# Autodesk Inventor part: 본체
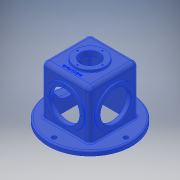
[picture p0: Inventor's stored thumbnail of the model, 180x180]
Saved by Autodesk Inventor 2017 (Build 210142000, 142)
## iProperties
Created: 2018-09
Part Number: 본체
Material: 알루미늄 6061
Document SubType Name: Modeling
Designer: mduedu
Density: 2.71 g/cm^3
Appearance: 기본값
Mass: 1123.29 g
Surface Area: 1247.23 cm^2
Volume: 414.5 cm^3
Author: mduedu
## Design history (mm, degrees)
sketch "스케치1"
  geometry: C1 r 90 at (0, 0); 1 further point
  constraints: 1 centre point, 1 coincident
  dimensions: "d85" = 180 diameter of C1
extrude "돌출1" new body sketch "스케치1" distance "d2" = 10; taper "d3" = 0 deg
sketch "스케치2"
  geometry: L1 (-52.5, -52.5)-(52.5, -52.5); L2 (52.5, -52.5)-(52.5, 52.5); L3 (52.5, 52.5)-(-52.5, 52.5); L4 (-52.5, 52.5)-(-52.5, -52.5); L5 (-52.5, -52.5)-(52.5, 52.5); L6 (52.5, -52.5)-(-52.5, 52.5); 1 further point
  constraints: 12 end point, 2 midpoint, 2 parallel, 1 horizontal, 1 perpendicular
  dimensions: "d4" = 105 distance of L3.end L2.end; "d5" = 105 distance of L2.end L1.end
extrude "돌출2" join sketch "스케치2" distance "d6" = 105; taper "d7" = 0 deg
node "작업 평면1"
sketch "스케치3"
  geometry: L1 (-52.5, 52.5)-(52.5, 52.5) reference; L2 (52.5, 52.5)-(52.5, -52.5) reference; L3 (52.5, -52.5)-(-52.5, -52.5) reference; L4 (-52.5, -52.5)-(-52.5, 52.5) reference; L5 (46.5, 46.5)-(-46.5, 46.5); L6 (-46.5, 46.5)-(-46.5, -46.5); L7 (-46.5, -46.5)-(46.5, -46.5); L8 (46.5, -46.5)-(46.5, 46.5); 1 further point
  constraints: 8 end point, 3 other
  dimensions: "d9" = 6 distance between parallel lines of L5 L1
extrude "돌출3" cut sketch "스케치3" stored distance "d10" = 105; taper "d11" = 0 deg
fillet "모깎기1" dims "d12" = 9
fillet "모깎기2" dims "d13" = 9
fillet "모깎기3" dims "d14" = 3
fillet "모깎기4" dims "d15" = 3
sketch "스케치4"
  geometry: C1 r 32 at (0, 0); 1 further point
  constraints: 1 centre point, 1 coincident
  dimensions: "d86" = 64 diameter of C1
extrude "돌출4" join sketch "스케치4" distance "d18" = 5; taper "d19" = 0 deg
fillet "모깎기6" dims "d21" = 1
sketch "스케치5"
  geometry: C1 r 20 at (0, 0); 1 further point
  constraints: 1 centre point, 1 coincident
  dimensions: "d22" = 40 diameter of C1
extrude "돌출5" cut sketch "스케치5" stored distance "d23" = 5; taper "d24" = 0 deg
sketch "스케치6"
  geometry: L1 (-46.5, -10)-(133.5, -10) reference; C1 r 42 at (43.5, 47.5); 1 further point
  constraints: 1 centre point, 1 vertical alignment
  dimensions: "d87" = 84 diameter of C1; "d88" = 57.5 distance from line of C1.centre L1
extrude "돌출6" join sketch "스케치6" distance "d28" = 3; taper "d29" = 0 deg
sketch "스케치7"
  geometry: C1 r 32.5 at (43.5, 47.5); 1 further point
  constraints: 1 centre point, 1 vertical alignment
  dimensions: "d32" = 65 diameter of C1; "d33" = 57.5 distance of C1.centre point (43.5, -10)
extrude "돌출7" cut sketch "스케치7" stored distance "d34" = 3; taper "d35" = 0 deg
fillet "모깎기9" dims "d36" = 1
sketch "스케치8"
  geometry: L1 (-46.5, -10)-(133.5, -10) reference; C1 r 32.5 at (43.5, 47.5); C2 r 42 at (43.5, 47.5); 4 further points
  constraints: 2 centre point, 2 coincident, 2 vertical alignment, 1 concentric, 1 midpoint
  dimensions: "d40" = 65 diameter of C1; "d90" = 84 diameter of C2; "d91" = 57.5 distance from line of point (43.5, 47.5) L1
extrude "돌출8" join sketch "스케치8" distance "d41" = 3; taper "d42" = 0 deg
extrude "돌출9" cut sketch "스케치8" stored distance "d44" = 3; taper "d45" = 0 deg
fillet "모깎기11" dims "d46" = 1
sketch "스케치14" dims "d93" = 74
  geometry: C1 r 42 at (0, 0) reference; 2 further points
  constraints: 2 vertical alignment, 1 coincident, 2 other
hole "구멍5" sketch "스케치14" at (0, 37) diameter "d95" = 3.242; stored, may be unused: countersink angle "d99" = 90 deg, drill point angle "d101" = 118 deg; dims "d96" = 6, "d97" = 4, "d98" = 2, "d100" = 8
sketch "스케치9" dims "d106" = 74
  geometry: C1 r 32.5 at (43.5, 47.5) reference; 2 further points
  constraints: 2 vertical alignment, 1 coincident, 2 other
hole "구멍1" sketch "스케치9" at (43.5, 84.5) diameter "d47" = 3.242; stored, may be unused: countersink angle "d51" = 90 deg, drill point angle "d53" = 118 deg; dims "d48" = 6, "d49" = 4, "d50" = 2, "d52" = 9
sketch "스케치11" dims "d110" = 54
  geometry: C1 r 20 at (0, 0) reference; 2 further points
  constraints: 2 horizontal alignment, 1 coincident, 2 other
hole "구멍3" sketch "스케치11" at (27, 0) diameter "d61" = 3.242; stored, may be unused: countersink angle "d65" = 90 deg, drill point angle "d67" = 118 deg; dims "d62" = 7, "d63" = 4, "d64" = 2, "d66" = 9
sketch "스케치12" dims "d115" = 155
  geometry: L1 (43.5, -52.5)-(-43.5, -52.5) reference; L2 (-52.5, -43.5)-(-52.5, 43.5) reference; L3 (-43.5, 52.5)-(43.5, 52.5) reference; L4 (52.5, 43.5)-(52.5, -43.5) reference; C1 r 90 at (0, 0) reference; A1 r 9 centre (-43.5, -43.5) between (-52.5, -43.5) and (-43.5, -52.5) reference; A2 r 9 centre (-43.5, 43.5) between (-43.5, 52.5) and (-52.5, 43.5) reference; A3 r 9 centre (43.5, 43.5) between (52.5, 43.5) and (43.5, 52.5) reference; A4 r 9 centre (43.5, -43.5) between (43.5, -52.5) and (52.5, -43.5) reference; 2 further points
  constraints: 2 horizontal alignment, 1 coincident, 2 other
hole "구멍4" sketch "스케치12" at (77.5, 0) diameter "d70" = 10; stored, may be unused: countersink angle "d74" = 90 deg, drill point angle "d76" = 118 deg; dims "d71" = 6, "d72" = 4, "d73" = 2, "d75" = 9
fillet "모깎기13" dims "d77" = 3
fillet "모깎기14" dims "d78" = 3
chamfer "모따기1" distance "d79" = 1; stored, may be unused: second distance "d80" = 2, angle "d81" = 45 deg
sketch "스케치15"
  geometry: 2 further points
  constraints: 1 horizontal alignment, 1 other
  dimensions: "d121" = 38 distance of point (38, 0) point (0, 0)
feature "엠보싱2" sketch "스케치15" dims "d2" = 10, "d3" = 0, "d9" = 6, "d122" = 0.5, "d123" = 0
node "솔리드1"
mirror "대칭1"
pattern_circular "원형 패턴1" dims angle "d104" = 360 deg
pattern_circular "원형 패턴2" dims angle "d108" = 360 deg
mirror "대칭2"
pattern_circular "원형 패턴3" dims angle "d113" = 360 deg
pattern_circular "원형 패턴4" dims angle "d119" = 360 deg
node "투영된 루프1"
node "투영된 루프2"
node "투영된 루프4"
node "투영된 루프5"
other parameters: "d8" = -6
